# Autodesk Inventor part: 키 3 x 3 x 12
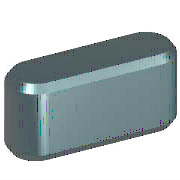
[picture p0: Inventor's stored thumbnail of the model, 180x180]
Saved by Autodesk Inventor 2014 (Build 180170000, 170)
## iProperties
Created: 2012-02
Part Number: 키 3 x 3 x 12
Material: 강철, 연강
Description: 키 및 해당 키홈
Document SubType Name: Modeling
Standard: KS B 1311
Designer: mduedu
Standards Organization: KS
Language: ko-KR
Size Designation: 3 x 3 x 12
Categories: <MemberInstance><Categories><Category DisplayName="샤프트 부품" InternalName="7f7aeb1f-a693-4053-b835-cee3144e0d98" Mnemonic="SHFT"><Category DisplayName="키" Interna
Density: 7.86 g/cm^3
Mass: 0.790122 g
Surface Area: 1.42216 cm^2
Volume: 0.100524 cm^3
Appearance: 노란색
IsCustomPart: 1
Author: mduedu
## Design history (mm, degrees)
workplane "Work Plane1"
workplane "Work Plane2"
sketch "스케치1"
  geometry: L1 (1.5, 1.5)-(10.5, 1.5); L2 (10.5, -1.5)-(1.5, -1.5); L3 (0, 9.4)-(0, -7.4) reference; L4 (-5, 0)-(30, 0) reference; L5 (12, 0)-(12, 7); A1 r 1.5 centre (1.5, 0) between (1.5, 1.5) and (1.5, -1.5); A2 r 1.5 centre (10.5, 0) between (10.5, -1.5) and (10.5, 1.5)
  constraints: 6 end point, 5 point on circle, 4 tangent, 3 point on line, 2 centre point, 1 horizontal, 1 parallel, 1 perpendicular
  dimensions: "d0" = 1.5 radius of A1 (= 0.5 x PB); "d13" = 1.5 radius of A2 (= 0.5 x PB); "d14" = 12 distance between parallel lines of L5 L3 (= NLG)
extrude "본체1" new body sketch "스케치1" taper "d3" = 0 deg; stored distance "d4" = 10
workplane "Work Plane3"
body "Solid1"
chamfer "모따기1" distance "d8" = 0.25 (= PHH); stored, may be unused: second distance "d9" = 0.25 (= PHH), angle "d15" = 45 deg
other parameters: "d1" = -1.8 (= -PNT), "d2" = 1.2 (= PH - PNT), "NLG" = 12 [user parameter; used in 3 equation terms], "PB" = 3 [user parameter; used in 2 equation terms], "PNT" = 1.8 [user parameter; used in 2 equation terms], "PH" = 3 [user parameter; used in 1 equation term], "PHH" = 0.25 [user parameter; used in 2 equation terms], "d10" = 0, "d16" = 0, "d17" = 0, "d18" = 0, "WDMIN" = 8 [user parameter], "PLB2" = 12 (= NLG) [user parameter], "PLB1" = 12 (= NLG) [user parameter], "RR" = 0.08 [user parameter], "PUEB" = 1.4 [user parameter]
